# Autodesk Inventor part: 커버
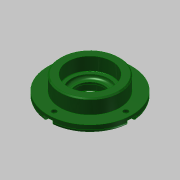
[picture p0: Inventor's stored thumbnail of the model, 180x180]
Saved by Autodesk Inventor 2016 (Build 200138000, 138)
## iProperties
Company: 한국ATC센터
Created: 2016-04
Part Number: 커버
Document SubType Name: Modeling
Designer: mdu
Density: 7.86 g/cm^3
Mass: 351.567 g
Surface Area: 161.165 cm^2
Volume: 44.7286 cm^3
Material: 강철, 연강
Appearance: 진녹색
Author: mdu
Revision Number: 1
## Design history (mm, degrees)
sketch "스케치1"
  geometry: C1 r 38 at (0, 0); 1 further point
  constraints: 1 centre point, 1 coincident
  dimensions: "d0" = 76 diameter of C1
extrude "돌출1" new body sketch "스케치1" distance "d1" = 7; taper "d2" = 0 deg
sketch "스케치2"
  geometry: C1 r 27 at (0, 0); 1 further point
  constraints: 1 centre point, 1 coincident
  dimensions: "d3" = 54 diameter of C1
extrude "돌출2" join sketch "스케치2" distance "d4" = 13; taper "d5" = 0 deg
sketch "스케치3"
  geometry: C1 r 20 at (0, 0); 1 further point
  constraints: 1 centre point, 1 coincident
  dimensions: "d6" = 40 diameter of C1
extrude "돌출3" join sketch "스케치3" distance "d7" = 5; taper "d8" = 0 deg
hole "구멍1" diameter "d11" = 25; stored, may be unused: countersink angle "d15" = 90 deg, drill point angle "d17" = 118 deg; dims "d9" = 10, "d10" = 10, "d12" = 6, "d13" = 32, "d14" = 8.3, "d16" = 8
hole "구멍2" diameter "d20" = 34; stored, may be unused: countersink angle "d24" = 90 deg, drill point angle "d26" = 0 deg; dims "d18" = 10, "d19" = 10, "d21" = 6, "d22" = 40, "d23" = 12, "d25" = 3
fillet "모깎기2" dims "d34" = 3
fillet "모깎기1" dims "d27" = 0.3
chamfer "모따기1" distance "d28" = 1; stored, may be unused: second distance "d29" = 2, angle "d30" = 45 deg
chamfer "모따기2" distance "d31" = 0.8; stored, may be unused: second distance "d32" = 2, angle "d33" = 30 deg
sketch "스케치4" dims "d35" = 65
  geometry: 3 further points
  constraints: 2 horizontal alignment, 1 coincident, 2 other
hole "구멍3" sketch "스케치4" at (32.5, 0) diameter "d36" = 4.5; stored, may be unused: countersink angle "d40" = 90 deg, drill point angle "d42" = 118 deg; dims "d37" = 6, "d38" = 8, "d39" = 4.4, "d41" = 13
sketch "스케치5"
  geometry: L1 (0, 4)-(5.5, 4); L2 (5.5, 4)-(5.5, -4); L3 (5.5, -4)-(0, -4); L4 (0, -4)-(0, 4); C1 r 2.25 at (0, 0) reference; C2 r 38 at (-32.5, 0) reference; 2 further points
  constraints: 8 end point, 3 horizontal, 2 parallel, 1 perpendicular, 1 tangent, 1 vertical alignment, 1 other
extrude "돌출4" cut sketch "스케치5" stored distance "d47" = 24.5; taper "d48" = 0 deg
node "솔리드1"
pattern_circular "원형 패턴1" dims angle "d44" = 360 deg
pattern_circular "원형 패턴2" dims angle "d50" = 360 deg
node "투영된 루프1"
